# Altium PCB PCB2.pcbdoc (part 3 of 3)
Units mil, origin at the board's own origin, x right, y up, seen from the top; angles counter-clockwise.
Board outline 1771.65 x 2755.61 mil, 4 copper layers (Top Layer, Inner1, Inner2, Bottom Layer), stack 62.447 mil thick; 80 components, 88 nets, 409 pads, 183 vias.
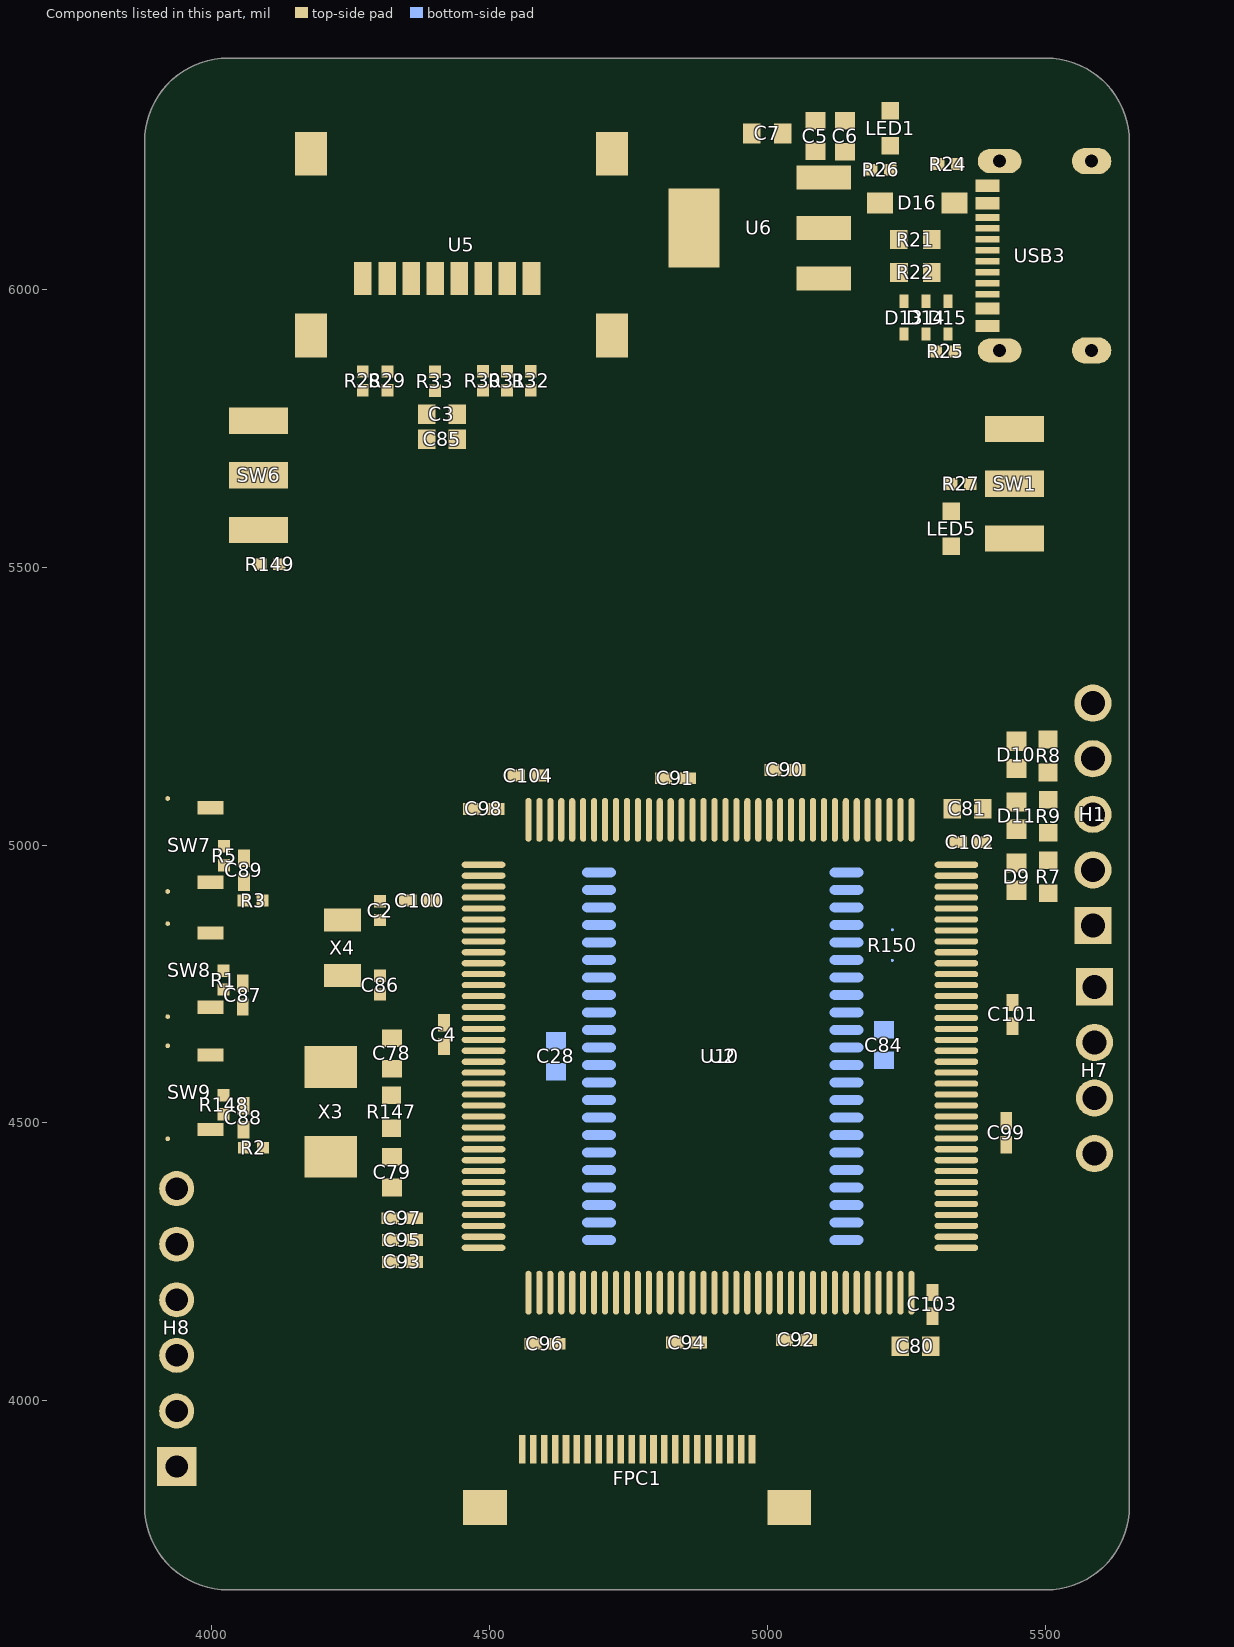
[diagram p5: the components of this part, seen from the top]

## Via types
v1: diameter 24.02, hole 12.01, Top Layer to Bottom Layer, 179 vias
v2: diameter 90.55, hole 82.68, Top Layer to Bottom Layer, 4 vias

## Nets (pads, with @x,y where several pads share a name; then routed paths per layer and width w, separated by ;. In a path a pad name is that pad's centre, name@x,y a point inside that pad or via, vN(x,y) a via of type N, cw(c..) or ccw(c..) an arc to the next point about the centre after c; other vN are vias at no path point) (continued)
pads on no net: H8.1 H8.2 U10.1 U10.2 U10.3 U10.4 U10.5 U10.7 U10.18 U10.19 U10.20 U10.21 U10.22 U10.26 U10.27 U10.28 U10.29 U10.44 U10.45 U10.46 U10.47 U10.48 U10.49 U10.69 U10.70 U10.73 U10.74 U10.75 U10.76 U10.91 U10.92 U10.93 U10.96 U10.97 U10.110 U10.117 U10.122 U10.124 U10.125 U10.126 U10.127 U10.128 U10.129 U10.132 U10.133 U10.134 U10.135 U10.136 U10.137 U10.139 U10.140 USB3.3 USB3.9

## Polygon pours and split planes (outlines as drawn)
NRST on Top Layer (solid, remove dead copper, pour order 6): 4045,4725 4035,4735 4035,4755 4015,4755 3980,4720 3970,4720 3970,4695 4040,4695 4045,4690 4065,4690 4070,4695 4070,4725
$1N25234 on Top Layer (solid, remove dead copper, pour order 8): 4035,4530 4035,4515 4045,4505 4070,4505 4070,4445 4046.71,4445 4016.71,4475 3975,4475 3970,4480 3970,4500 4005,4500 4010,4505 4010,4530
$1N25235 on Top Layer (solid, remove dead copper, pour order 10): 4045.97,4889.03 4015,4920 3975,4920 3970,4925 3970,4940 3975,4945 4005,4945 4010,4950 4010,4975 4035,4975 4035,4960 4045,4950 4070,4950 4070,4889.03
$1N4774 on Top Layer (solid, remove dead copper, pour order 12): 5545,5535 5535,5525 5395,5525 5390,5530 5390,5575 5395,5580 5535,5580 5545,5570
3.3V on Top Layer (solid, remove dead copper, pour order 14): 5300,4990 5300,4960 5305,4955 5375,4955 5385,4965 5385,4970.28 5360.28,4995 5360,4995 5360,5020.14 5330.14,5020.14
$1N4201 on Top Layer (solid, pour order 0): 5328.92,5954.53 5317.05,5966.4 5317.05,5990.07 5317.06,5990.07 5361.11,5990.07 5374.75,5976.43 5427.54,5976.43 5430.42,5973.54 5430.42,5965.98 5418.98,5954.53
5V_USB on Top Layer (solid, pour order 2): 5136.9,6178.59 5052.49,6178.59 5052.49,6252.34 5067.49,6267.35 5158.67,6267.35 5227.04,6198.98 5227.04,6136.5 5226.8,6136.26 5179.23,6136.26
$1N4593 on Top Layer (solid, pour order 4): 4990,6300 4990,6195 5050,6135 5150,6135 5155,6130 5155,6090 5150,6085 4965,6085 4915,6035 4825,6035 4820,6040 4820,6180 4825,6185 4880,6185 4955,6260 4955,6300
3.3V on Top Layer (solid, remove dead copper, pour order 16): 5285,4235 5255,4235 5253.19,4233.19 5253.19,4158.99 5257.15,4155.04 5262.48,4155.04 5285.73,4178.29 5310.09,4178.29 5310.11,4178.31 5310.11,4209.89
3.3V on Top Layer (solid, remove dead copper, pour order 18): 4530,4360 4530,4332.35 4526.42,4328.78 4399.28,4328.78 4382.24,4311.73 4382.24,4238.13 4350.18,4238.13 4348.8,4239.51 4348.8,4340.25 4368.49,4359.94 4482.22,4359.94 4482.28,4360
3.3V on Top Layer (solid, remove dead copper, pour order 20): 4575,5005 4540,5005 4495,5050 4495,5080 4500,5085 4580,5085 4580,5010
5V_USB on Top Layer (solid, remove dead copper, pour order 22): 4825,3890 4830,3885 4980,3885 4985,3890 4985,3935 4980,3940 4830,3940 4825,3935
GND on Top Layer (solid, remove dead copper, pour order 24): 3710,6670 6060,6670 6060,3550 3710,3550
GND on Bottom Layer (solid, remove dead copper, pour order 26): 3595,6825 6195,6825 6195,3000 3595,3000
GND on Inner1 (solid, remove dead copper): 3345,6830 6970,6830 6970,3350 3345,3350
GND on Inner2 (solid, remove dead copper): 3000,6645 7185,6645 7185,3075 3000,3075
5V_USB on Inner2 (solid, remove dead copper): 5145,6240 5195,6240 5210,6225 5210,6180 5205,6175 5145,6175

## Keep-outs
Board Outline Layer:
  the board outline again, w10

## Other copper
Top Layer:
  drawing of 189 lines, arcs and shapes, not listed
Inner1:
  region net 3.3V: 5519.95,4703.19 5519.95,4726.81 ccw(c5519.95,4771.1) 5555.39,4744.53 5555.39,4711.44 ccw(c5555.39,4631.28)
  region net 3.3V: 5536.74,4756.55 5526.8,4799.9 ccw(c5617.53,4890.63) 5555.39,4778.37 5555.39,4725.09 ccw(c5484.59,4704.4)
  region net NRST: 4426.35,4493 4426.35,4487 4424.82,4486.87 4423.6,4486.48 4422.59,4485.89 4421.72,4485.12 4420.05,4483.2 4417.94,4480.99 4417.94,4499.01 4420.05,4496.8 4421.72,4494.88 4422.59,4494.11 4423.6,4493.52 4424.82,4493.13
  region net A2: 4990.3,4860.86 4984.3,4860.86 4984.16,4862.39 4983.78,4863.61 4983.19,4864.62 4982.42,4865.49 4980.5,4867.16 4978.29,4869.27 4996.31,4869.27 4994.1,4867.16 4992.18,4865.49 4991.41,4864.62 4990.82,4863.61 4990.43,4862.39
  region net A1: 4963.19,4834.15 4957.19,4834.15 4957.05,4835.68 4956.67,4836.9 4956.08,4837.91 4955.31,4838.78 4953.39,4840.45 4951.18,4842.56 4969.2,4842.56 4966.99,4840.45 4965.07,4838.78 4964.3,4837.91 4963.71,4836.9 4963.32,4835.68
  region net A0: 4611.35,4793 4611.35,4787 4609.82,4786.87 4608.6,4786.48 4607.59,4785.89 4606.72,4785.12 4605.05,4783.2 4602.94,4780.99 4602.94,4799.01 4605.05,4796.8 4606.72,4794.88 4607.59,4794.11 4608.6,4793.52 4609.82,4793.13
  region net IO7: 5086.8,4460.32 5082.56,4464.56 5083.54,4465.74 5084.14,4466.87 5084.43,4468 5084.51,4469.16 5084.32,4471.7 5084.26,4474.75 5096.99,4462.02 5093.94,4462.08 5091.4,4462.26 5090.24,4462.19 5089.11,4461.9 5087.98,4461.3
  region net IO7: 5077,4300.56 5083,4302.08 5083.14,4300.59 5083.54,4299.35 5084.17,4298.3 5084.97,4297.37 5087,4295.65 5089.32,4293.68 5071.37,4292.15 5072.42,4293.41 5073.44,4294.4 5075.24,4296 5075.96,4296.82 5076.52,4297.78 5076.87,4298.99
  region net NRST: 5458.65,4917 5458.65,4923 5460.18,4923.13 5461.4,4923.52 5462.41,4924.11 5463.28,4924.88 5464.95,4926.8 5467.06,4929.01 5467.06,4910.99 5464.95,4913.2 5463.28,4915.12 5462.41,4915.89 5461.4,4916.48 5460.18,4916.87
  region net 3.3V: 4640.16,4100.88 4623.45,4084.18 4613.13,4094.23 4630.11,4111.21
  region net 3.3V: 4835.59,4053.19 4835.59,4076.81 4850,4077.01 4850,4052.99
  region net 3.3V: 5424.41,4726.81 5424.41,4703.19 5410,4702.99 5410,4727.01
  region net 3.3V: 4376.46,4926.84 4393.16,4943.54 4403.49,4933.49 4386.51,4916.51
  region net 3.3V: 4114.41,4991.81 4114.41,4968.19 4100,4967.99 4100,4992.01
  region net 3.3V: 5338.22,4968.19 5338.22,4991.81 5352.63,4992.01 5352.63,4967.99
  region net 3.3V: 5367.04,4991.81 5367.04,4968.19 5352.63,4967.99 5352.63,4992.01
  region net 3.3V: 5226.84,4918.54 5243.54,4901.84 5233.49,4891.51 5216.51,4908.49
Inner2:
  region net 3.3V: 5542.86,4774.2 5559.56,4790.9 ccw(c5597.14,4841.01) 5597.14,4778.37 5555.39,4736.62 ccw(c5492.75,4736.62)
  region net A18: 4770.9,4448.05 4769.98,4442.05 4768.39,4441.93 4767.18,4441.59 4766.25,4441.07 4765.48,4440.39 4763.92,4438.68 4762.9,4437.72 4761.57,4436.72 4764.15,4454.55 4765.06,4453.34 4765.77,4452.16 4766.96,4450.08 4767.62,4449.25 4768.44,4448.61 4769.5,4448.2
  region net A18: 5378.22,4450.01 5379.28,4456.01 5380.83,4456.14 5382.05,4456.5 5383.03,4457.07 5383.86,4457.8 5385.48,4459.65 5386.46,4460.68 5387.69,4461.76 5386.62,4443.78 5384.61,4446.06 5382.9,4448.06 5381.99,4448.86 5380.95,4449.47 5379.72,4449.87
  region net CS: 4998.68,4985.56 4994.44,4981.32 4993.27,4982.31 4992.13,4982.9 4991,4983.2 4989.84,4983.27 4987.3,4983.08 4984.25,4983.02 4996.98,4995.75 4996.92,4992.7 4996.73,4990.16 4996.8,4989 4997.1,4987.87 4997.69,4986.73
  region net CS: 5213.65,4812.01 5213.65,4817.99 5215.18,4818.13 5216.4,4818.51 5217.41,4819.1 5218.28,4819.87 5219.95,4821.8 5222.06,4824.01 5222.06,4805.99 5219.95,4808.2 5218.28,4810.13 5217.41,4810.9 5216.4,4811.49 5215.18,4811.87
  region net 5V_USB: 5171.81,6175.59 5148.19,6175.59 5147.99,6190 5172.01,6190
  region net 5V_USB: 5009.41,3936.81 5009.41,3913.19 4995,3912.99 4995,3937.01
  region net 3.3V: 5526.81,5635.59 5503.19,5635.59 5502.99,5650 5527.01,5650
Bottom Layer:
  region net $1N4774: 5617.23,4894.99 5625.58,4886.64 ccw(c5650.64,4867.84) 5619.32,4867.84 5598.44,4888.72 ccw(c5598.44,4920.04)
  region net GND: 4646.72,4638.75 4646.72,4632.75 ccw(c4646.72,4589.1) 4637.72,4631.81 4637.72,4643.25 ccw(c4646.72,4650)
  region net 3.3V: 4605.86,4568.34 4593.93,4578.69 ccw(c4560.53,4603.74) 4602.28,4603.74 4630.91,4576.69 ccw(c4630.91,4534.93)
  region net 3.3V: 4646.72,4607.25 4646.72,4601.25 ccw(c4646.72,4590) 4637.72,4596.75 4637.72,4608.19 ccw(c4646.72,4650.9)
  region net 3.3V: 4593.93,4607.37 4607.04,4616.54 ccw(c4632.09,4649.95) 4632.09,4608.19 4602.28,4582.32 ccw(c4560.53,4582.32)
  region net GND: 5183.28,4601.25 5183.28,4607.25 ccw(c5183.28,4618.5) 5192.28,4611.75 5192.28,4596.75 ccw(c5183.28,4590)
  region net GND: 5233.19,4607.25 5233.19,4601.25 ccw(c5233.19,4595.67) 5227.72,4596.75 5227.72,4611.75 ccw(c5233.19,4612.83)
  region net 3.3V: 5196.32,4647.08 5186.06,4645.31 ccw(c5044.31,4787.05) 5192.28,4651.81 5204.31,4651.81 ccw(c5209.57,4633.83)
  region net 3.3V: 5263.15,4679.37 5263.15,4655.75 ccw(c5263.15,4494.33) 5227.72,4651.81 5227.72,4683.31 ccw(c5263.15,4840.79)
  region net 3.3V: 3963.29,4420 3976.76,4400.06 3974.62,4397.58 3972.99,4394.99 3971.76,4392.28 3970.86,4389.45 3970.2,4386.5 3969.67,4383.43 3968.71,4376.92 3938.7,4413.41 3942,4413.35 3945.35,4413.45 3948.68,4413.74 3951.95,4414.28 3955.1,4415.13 3958.08,4416.33 3960.83,4417.93
  region net A4: 5107.31,4947.71 5107.31,4953.71 5108.77,4953.81 5110.01,4954.1 5111.08,4954.54 5112.05,4955.12 5113.97,4956.56 5116.31,4958.21 5116.31,4943.21 5113.97,4944.86 5112.05,4946.3 5111.08,4946.88 5110.01,4947.32 5108.77,4947.61
  region net A3: 5108.25,4916.21 5108.25,4922.21 5109.68,4922.31 5110.8,4922.6 5111.72,4923.04 5112.52,4923.62 5114.12,4925.06 5116.31,4926.71 5116.31,4911.71 5114.12,4913.36 5112.52,4914.8 5111.72,4915.38 5110.8,4915.82 5109.68,4916.11
  region net A1: 5107.31,4853.22 5107.31,4859.22 5108.77,4859.32 5110.01,4859.61 5111.08,4860.05 5112.05,4860.63 5113.97,4862.07 5116.31,4863.72 5116.31,4848.72 5113.97,4850.37 5112.05,4851.81 5111.08,4852.39 5110.01,4852.83 5108.77,4853.12
  region net A0: 5107.31,4821.72 5107.31,4827.72 5108.77,4827.82 5110.01,4828.11 5111.08,4828.55 5112.05,4829.13 5113.97,4830.57 5116.31,4832.22 5116.31,4817.22 5113.97,4818.87 5112.05,4820.31 5111.08,4820.89 5110.01,4821.33 5108.77,4821.62
  region net CS: 5178.01,4796.23 5178.01,4790.23 5176.55,4790.13 5175.31,4789.84 5174.24,4789.4 5173.27,4788.82 5171.35,4787.38 5169.01,4785.73 5169.01,4800.73 5171.35,4799.08 5173.27,4797.64 5174.24,4797.06 5175.31,4796.62 5176.55,4796.33
  region net IO0: 5178.01,4764.73 5178.01,4758.73 5176.55,4758.63 5175.31,4758.34 5174.24,4757.9 5173.27,4757.32 5171.35,4755.88 5169.01,4754.23 5169.01,4769.23 5171.35,4767.58 5173.27,4766.14 5174.24,4765.56 5175.31,4765.12 5176.55,4764.83
  region net IO1: 5178.01,4733.24 5178.01,4727.24 5176.55,4727.14 5175.31,4726.85 5174.24,4726.41 5173.27,4725.83 5171.35,4724.39 5169.01,4722.74 5169.01,4737.74 5171.35,4736.09 5173.27,4734.65 5174.24,4734.07 5175.31,4733.63 5176.55,4733.34
  region net IO2: 5178.01,4701.74 5178.01,4695.74 5176.55,4695.64 5175.31,4695.35 5174.24,4694.91 5173.27,4694.33 5171.35,4692.89 5169.01,4691.24 5169.01,4706.24 5171.35,4704.59 5173.27,4703.15 5174.24,4702.57 5175.31,4702.13 5176.55,4701.84
  region net IO3: 5107.31,4664.24 5107.31,4670.24 5108.77,4670.34 5110.01,4670.63 5111.08,4671.07 5112.05,4671.65 5113.97,4673.09 5116.31,4674.74 5116.31,4659.74 5113.97,4661.39 5112.05,4662.83 5111.08,4663.41 5110.01,4663.85 5108.77,4664.14
  region net 3.3V: 5178.01,4638.75 5178.01,4632.75 5176.55,4632.65 5175.31,4632.36 5174.24,4631.92 5173.27,4631.34 5171.35,4629.9 5169.01,4628.25 5169.01,4643.25 5171.35,4641.6 5173.27,4640.16 5174.24,4639.58 5175.31,4639.14 5176.55,4638.85
  region net GND: 5178.01,4607.25 5178.01,4601.25 5176.55,4601.15 5175.31,4600.86 5174.24,4600.42 5173.27,4599.84 5171.35,4598.4 5169.01,4596.75 5169.01,4611.75 5171.35,4610.1 5173.27,4608.66 5174.24,4608.08 5175.31,4607.64 5176.55,4607.35
  region net IO4: 5108.39,4568.54 5106.31,4574.54 5107.7,4574.65 5108.95,4574.97 5110.09,4575.46 5111.15,4576.1 5113.19,4577.7 5115.31,4579.54 5117.39,4564.69 5115.95,4565.41 5114.82,4566.1 5113.05,4567.33 5112.19,4567.83 5111.2,4568.21 5109.97,4568.45
  region net IO5: 5107.31,4538.26 5107.31,4544.26 5108.77,4544.36 5110.01,4544.65 5111.08,4545.09 5112.05,4545.67 5113.97,4547.11 5116.31,4548.76 5116.31,4533.76 5113.97,4535.41 5112.05,4536.85 5111.08,4537.43 5110.01,4537.87 5108.77,4538.16
  region net IO6: 5107.31,4506.76 5107.31,4512.76 5108.77,4512.86 5110.01,4513.15 5111.08,4513.59 5112.05,4514.17 5113.97,4515.61 5116.31,4517.26 5116.31,4502.26 5113.97,4503.91 5112.05,4505.35 5111.08,4505.93 5110.01,4506.37 5108.77,4506.66
  region net IO7: 5105.93,4477 5108.87,4483 5109.89,4483.12 5111.01,4483.43 5113.43,4484.44 5115.82,4485.61 5117.87,4486.53 5114.93,4471.83 5112.89,4473.73 5110.81,4475.38 5109.71,4476.05 5108.54,4476.56 5107.29,4476.88
  region net WE: 5107.31,4443.77 5107.31,4449.77 5108.77,4449.87 5110.01,4450.16 5111.08,4450.6 5112.05,4451.18 5113.97,4452.62 5116.31,4454.27 5116.31,4439.27 5113.97,4440.92 5112.05,4442.36 5111.08,4442.94 5110.01,4443.38 5108.77,4443.67
  region net A16: 5178.01,4418.28 5178.01,4412.28 5176.55,4412.18 5175.31,4411.89 5174.24,4411.45 5173.27,4410.87 5171.35,4409.43 5169.01,4407.78 5169.01,4422.78 5171.35,4421.13 5173.27,4419.69 5174.24,4419.11 5175.31,4418.67 5176.55,4418.38
  region net A15: 5173.7,4386.78 5173.7,4380.78 5172.96,4380.63 5172.32,4380.24 5171.23,4378.95 5170.21,4377.46 5169.65,4376.8 5169.01,4376.28 5169.01,4391.28 5169.65,4390.76 5170.21,4390.1 5171.23,4388.61 5172.32,4387.32 5172.96,4386.93
  region net A5: 4732.69,4953.71 4732.69,4947.71 4731.23,4947.61 4729.99,4947.32 4728.92,4946.88 4727.95,4946.3 4726.03,4944.86 4723.69,4943.21 4723.69,4958.21 4726.03,4956.56 4727.95,4955.12 4728.92,4954.54 4729.99,4954.1 4731.23,4953.81
  region net A7: 4729.52,4890.72 4729.52,4884.72 4728.73,4884.57 4727.97,4884.18 4726.49,4882.89 4725.07,4881.4 4723.69,4880.22 4723.69,4895.22 4725.07,4894.04 4726.49,4892.55 4727.97,4891.26 4728.73,4890.87
  region net UB: 4661.99,4821.72 4661.99,4827.72 4663.45,4827.82 4664.69,4828.11 4665.76,4828.55 4666.73,4829.13 4668.65,4830.57 4670.99,4832.22 4670.99,4817.22 4668.65,4818.87 4666.73,4820.31 4665.76,4820.89 4664.69,4821.33 4663.45,4821.62
  region net LB: 4661.99,4790.23 4661.99,4796.23 4663.45,4796.33 4664.69,4796.62 4665.76,4797.06 4666.73,4797.64 4668.65,4799.08 4670.99,4800.73 4670.99,4785.73 4668.65,4787.38 4666.73,4788.82 4665.76,4789.4 4664.69,4789.84 4663.45,4790.13
  region net IO15: 4732.69,4764.73 4732.69,4758.73 4731.23,4758.63 4729.99,4758.34 4728.92,4757.9 4727.95,4757.32 4726.03,4755.88 4723.69,4754.23 4723.69,4769.23 4726.03,4767.58 4727.95,4766.14 4728.92,4765.56 4729.99,4765.12 4731.23,4764.83
  region net IO14: 4732.69,4733.24 4732.69,4727.24 4731.23,4727.14 4729.99,4726.85 4728.92,4726.41 4727.95,4725.83 4726.03,4724.39 4723.69,4722.74 4723.69,4737.74 4726.03,4736.09 4727.95,4734.65 4728.92,4734.07 4729.99,4733.63 4731.23,4733.34
  region net IO13: 4732.69,4701.74 4732.69,4695.74 4731.23,4695.64 4729.99,4695.35 4728.92,4694.91 4727.95,4694.33 4726.03,4692.89 4723.69,4691.24 4723.69,4706.24 4726.03,4704.59 4727.95,4703.15 4728.92,4702.57 4729.99,4702.13 4731.23,4701.84
  region net IO12: 4732.69,4670.24 4732.69,4664.24 4731.23,4664.14 4729.99,4663.85 4728.92,4663.41 4727.95,4662.83 4726.03,4661.39 4723.69,4659.74 4723.69,4674.74 4726.03,4673.09 4727.95,4671.65 4728.92,4671.07 4729.99,4670.63 4731.23,4670.34
  region net GND: 4661.99,4632.75 4661.99,4638.75 4663.45,4638.85 4664.69,4639.14 4665.76,4639.58 4666.73,4640.16 4668.65,4641.6 4670.99,4643.25 4670.99,4628.25 4668.65,4629.9 4666.73,4631.34 4665.76,4631.92 4664.69,4632.36 4663.45,4632.65
  region net 3.3V: 4661.99,4601.25 4661.99,4607.25 4663.45,4607.35 4664.69,4607.64 4665.76,4608.08 4666.73,4608.66 4668.65,4610.1 4670.99,4611.75 4670.99,4596.75 4668.65,4598.4 4666.73,4599.84 4665.76,4600.42 4664.69,4600.86 4663.45,4601.15
  region net IO11: 4732.69,4575.76 4732.69,4569.76 4731.23,4569.66 4729.99,4569.37 4728.92,4568.93 4727.95,4568.35 4726.03,4566.91 4723.69,4565.26 4723.69,4580.26 4726.03,4578.61 4727.95,4577.17 4728.92,4576.59 4729.99,4576.15 4731.23,4575.86
  region net IO10: 4732.69,4544.26 4732.69,4538.26 4731.23,4538.16 4729.99,4537.87 4728.92,4537.43 4727.95,4536.85 4726.03,4535.41 4723.69,4533.76 4723.69,4548.76 4726.03,4547.11 4727.95,4545.67 4728.92,4545.09 4729.99,4544.65 4731.23,4544.36
  region net IO9: 4732.69,4512.76 4732.69,4506.76 4731.23,4506.66 4729.99,4506.37 4728.92,4505.93 4727.95,4505.35 4726.03,4503.91 4723.69,4502.26 4723.69,4517.26 4726.03,4515.61 4727.95,4514.17 4728.92,4513.59 4729.99,4513.15 4731.23,4512.86
  region net IO8: 4733.55,4480.22 4731.77,4474.22 4730.21,4474.13 4728.98,4473.88 4727.98,4473.49 4727.1,4472.99 4725.31,4471.72 4722.77,4470.27 4724.55,4485.17 4726.71,4483.35 4728.73,4481.77 4729.78,4481.13 4730.91,4480.65 4732.15,4480.33
  region net A18: 4732.69,4449.77 4732.69,4443.77 4731.23,4443.67 4729.99,4443.38 4728.92,4442.94 4727.95,4442.36 4726.03,4440.92 4723.69,4439.27 4723.69,4454.27 4726.03,4452.62 4727.95,4451.18 4728.92,4450.6 4729.99,4450.16 4731.23,4449.87
  region net A8: 4732.69,4418.28 4732.69,4412.28 4731.23,4412.18 4729.99,4411.89 4728.92,4411.45 4727.95,4410.87 4726.03,4409.43 4723.69,4407.78 4723.69,4422.78 4726.03,4421.13 4727.95,4419.69 4728.92,4419.11 4729.99,4418.67 4731.23,4418.38
  region net A11: 4729.9,4324.6 4729.9,4318.6 4729.15,4318.45 4728.41,4318.02 4726.98,4316.63 4725.62,4315.02 4724.36,4313.75 4722.98,4328.69 4724.6,4327.62 4726.35,4326.26 4728.14,4325.1 4729.03,4324.74
  region net A17: 4732.8,4292.16 4732.58,4286.16 4731.1,4286.06 4729.87,4285.78 4728.81,4285.34 4727.85,4284.77 4725.94,4283.35 4723.58,4281.72 4723.8,4296.72 4726.12,4295.04 4728.05,4293.58 4729.04,4293 4730.11,4292.55 4731.35,4292.26
  region net 3.3V: 5213.19,4896.6 5236.81,4896.6 ccw(c6236.71,4896.6) 5237.44,4861.17 5236.81,4861.28 5213.19,4861.28 5212.57,4861.17 ccw(c4205.26,4896.6)
  region net CS: 5199.07,4790.23 5199.07,4796.23 ccw(c5199.07,4808.19) 5208.07,4800.32 5208.07,4796.23 5208.07,4790.23 5208.07,4785.73 ccw(c5199.07,4778.98)
  region net CS: 5222.01,4810 5227.99,4810 ccw(c5232.48,4810.78) 5232.48,4806.22 5227.99,4806.22 5222.01,4806.22 5217.52,4806.22 ccw(c5217.52,4810.78)
  region net $1N4774: 5546.35,5560.91 5546.35,5549.09 5544.26,5548.84 5541.92,5548.15 5539.69,5547.16 5537.94,5545.99 5537.94,5564.01 5539.69,5562.84 5541.92,5561.85 5544.26,5561.16
  region net DAISY: 4714.39,4148.65 4720.39,4148.65 4720.52,4147.12 4720.9,4145.9 4721.5,4144.89 4722.26,4144.02 4724.19,4142.35 4726.39,4140.24 4708.38,4140.24 4710.59,4142.35 4712.51,4144.02 4713.28,4144.89 4713.87,4145.9 4714.25,4147.12
  region net DAISY: 4558.68,4285.56 4554.44,4281.32 4553.26,4282.3 4552.13,4282.9 4551,4283.19 4549.84,4283.26 4547.3,4283.08 4544.25,4283.02 4556.98,4295.75 4556.92,4292.7 4556.74,4290.16 4556.81,4289 4557.1,4287.87 4557.7,4286.74
  region net USB_OTG_FS_DM: 5432.07,4864.08 5432.07,4858.08 5430.54,4857.94 5429.32,4857.56 5428.31,4856.97 5427.44,4856.2 5425.77,4854.27 5423.66,4852.07 5423.66,4870.08 5425.77,4867.88 5427.44,4865.95 5428.31,4865.18 5429.32,4864.59 5430.54,4864.21
  region net USB_OTG_FS_DP: 5432.19,4894.18 5432.19,4888.18 5430.67,4888.04 5429.44,4887.66 5428.44,4887.07 5427.56,4886.3 5425.9,4884.38 5423.79,4882.17 5423.79,4900.18 5425.9,4897.98 5427.56,4896.05 5428.44,4895.29 5429.44,4894.69 5430.67,4894.31
  region net USB_OTG_FS_DM: 5339.68,5812.07 5333.68,5800.42 5333.57,5801.87 5333.25,5803.29 5332.74,5804.65 5332.03,5805.89 5331.15,5806.98 5330.09,5807.86 5328.88,5808.49 5327.53,5808.83 5340.95,5820.48 5340.71,5817.97 5340.28,5816.27 5339.87,5814.58
  region net RST(ADS8688): 4813.14,3978 4813.14,3972 4811.61,3971.87 4810.39,3971.48 4809.38,3970.89 4808.51,3970.12 4806.84,3968.2 4804.73,3965.99 4804.73,3984.01 4806.84,3981.8 4808.51,3979.88 4809.38,3979.11 4810.39,3978.52 4811.61,3978.13
  region net RST(ADS8688): 5423.68,4785.56 5419.44,4781.32 5418.26,4782.3 5417.13,4782.9 5416,4783.19 5414.84,4783.26 5412.3,4783.08 5409.25,4783.02 5421.98,4795.75 5421.92,4792.7 5421.74,4790.16 5421.81,4789 5422.1,4787.87 5422.7,4786.74
  region net WKUP: 4408.65,4302 4408.65,4308 4410.18,4308.13 4411.4,4308.52 4412.41,4309.11 4413.28,4309.88 4414.95,4311.8 4417.06,4314.01 4417.06,4295.99 4414.95,4298.2 4413.28,4300.12 4412.41,4300.89 4411.4,4301.48 4410.18,4301.87
  region net WKUP: 4096.02,4417.41 4090.02,4417.41 4089.89,4418.94 4089.5,4420.16 4088.91,4421.17 4088.14,4422.04 4086.22,4423.71 4084.01,4425.82 4102.03,4425.82 4099.82,4423.71 4097.9,4422.04 4097.13,4421.17 4096.54,4420.16 4096.16,4418.94
  region net NRST: 4095.31,4695.56 4091.07,4691.32 4089.89,4692.3 4088.76,4692.9 4087.63,4693.19 4086.47,4693.26 4083.93,4693.08 4080.88,4693.02 4093.61,4705.75 4093.55,4702.7 4093.36,4700.16 4093.44,4699 4093.73,4697.87 4094.33,4696.74
  region net NRST: 4396.32,4499.44 4400.56,4503.68 4401.74,4502.7 4402.87,4502.1 4404,4501.81 4405.16,4501.74 4407.7,4501.92 4410.75,4501.98 4398.02,4489.25 4398.08,4492.3 4398.26,4494.84 4398.19,4496 4397.9,4497.13 4397.3,4498.26
  region net UB: 4639.4,4967.51 4633.4,4967.51 4633.26,4968.9 4632.86,4969.91 4632.23,4970.64 4631.41,4971.19 4629.36,4972.21 4628.21,4972.89 4627.02,4973.82 4644.93,4975.72 4643.9,4974.45 4642.9,4973.47 4641.13,4971.95 4640.42,4971.18 4639.88,4970.26 4639.53,4969.07
  region net A5: 4783.08,4947.71 4783.57,4953.71 4785.1,4953.84 4786.32,4954.22 4787.32,4954.8 4788.17,4955.55 4789.81,4957.43 4790.78,4958.49 4791.97,4959.59 4791.44,4941.59 4789.38,4943.84 4787.71,4945.8 4786.83,4946.58 4785.82,4947.18 4784.59,4947.57
  region net A6: 4808.65,4916.21 4808.65,4922.21 4810.18,4922.34 4811.4,4922.73 4812.41,4923.32 4813.28,4924.09 4814.95,4926.01 4817.06,4928.22 4817.06,4910.2 4814.95,4912.41 4813.28,4914.33 4812.41,4915.1 4811.4,4915.69 4810.18,4916.08
  region net IO13: 4973.88,4692.66 4978.12,4696.91 4979.3,4695.92 4980.43,4695.33 4981.56,4695.03 4982.72,4694.96 4985.26,4695.14 4988.31,4695.21 4975.58,4682.47 4975.65,4685.53 4975.83,4688.06 4975.75,4689.22 4975.46,4690.35 4974.86,4691.49
  region net IO12: 5025.2,4490.56 5028.13,4496.11 5029.29,4495.16 5030.45,4494.57 5031.65,4494.26 5032.88,4494.18 5035.56,4494.39 5038.59,4494.67 5027.22,4480.7 5027.05,4482.33 5027.05,4483.75 5027.18,4486.13 5027.11,4487.2 5026.83,4488.26 5026.22,4489.36
  region net IO11: 5025.39,4438.08 5029.63,4442.32 5030.8,4441.34 5031.94,4440.74 5033.07,4440.45 5034.23,4440.38 5036.77,4440.56 5039.82,4440.63 5027.08,4427.89 5027.15,4430.94 5027.33,4433.48 5027.26,4434.64 5026.97,4435.77 5026.37,4436.91
  region net IO8: 5023.38,4329.07 5022.47,4335.07 5023.98,4335.21 5025.21,4335.6 5026.24,4336.22 5027.15,4337.01 5028.85,4338.99 5030.88,4341.27 5031.78,4323.28 5030.57,4324.36 5029.59,4325.41 5027.96,4327.26 5027.12,4328 5026.14,4328.57 5024.92,4328.94
  region net A9: 4911.06,4380.78 4911.28,4386.78 4912.81,4386.91 4914.04,4387.29 4915.04,4387.88 4915.9,4388.64 4917.56,4390.55 4918.52,4391.62 4919.69,4392.73 4919.47,4374.72 4917.38,4376.95 4915.7,4378.89 4914.82,4379.66 4913.81,4380.26 4912.58,4380.64
  region net A11: 4956.32,4307.08 4951.88,4311.12 4952.85,4312.29 4953.45,4313.43 4953.74,4314.57 4953.82,4315.74 4953.63,4318.3 4953.53,4321.35 4966.46,4308.82 4964.85,4308.77 4963.41,4308.85 4960.89,4309.03 4959.75,4308.95 4958.63,4308.66 4957.5,4308.06
  region net A3: 4769.8,4817.4 4769.8,4811.4 4769.01,4811.2 4768.33,4810.67 4767.73,4809.89 4767.19,4808.96 4766.15,4806.96 4765.6,4806.08 4765,4805.39 4765,4823.4 4765.6,4822.71 4766.15,4821.83 4767.19,4819.84 4767.73,4818.9 4768.33,4818.12 4769.01,4817.59
  region net A0: 4950.15,4827.72 4955.55,4821.72 4954.13,4821.57 4952.85,4821.13 4951.68,4820.46 4950.62,4819.59 4948.76,4817.41 4947.14,4814.91 4941.74,4832.09 4943.71,4830.95 4945.86,4829.5 4948.04,4828.25 4949.11,4827.86
  region net IO0: 5187.44,4758.73 5190.03,4764.73 5191.63,4764.85 5192.83,4765.19 5193.76,4765.71 5194.53,4766.39 5196.09,4768.1 5197.1,4769.06 5198.44,4770.06 5195.84,4752.23 5193.97,4754.62 5192.2,4756.7 5191.24,4757.53 5190.16,4758.17 5188.91,4758.58
  region net IO1: 5209.64,4727 5209.64,4733 5211.17,4733.13 5212.39,4733.52 5213.4,4734.11 5214.27,4734.88 5215.94,4736.8 5218.05,4739.01 5218.05,4720.99 5215.94,4723.2 5214.27,4725.12 5213.4,4725.89 5212.39,4726.48 5211.17,4726.87
  region net IO2: 5163.65,4695.74 5163.65,4701.74 5165.18,4701.87 5166.4,4702.26 5167.41,4702.85 5168.28,4703.62 5169.95,4705.54 5172.06,4707.75 5172.06,4689.73 5169.95,4691.94 5168.28,4693.86 5167.41,4694.63 5166.4,4695.22 5165.18,4695.61
  region net IO3: 5111.35,4670.24 5111.35,4664.24 5109.82,4664.11 5108.6,4663.72 5107.59,4663.13 5106.72,4662.36 5105.05,4660.44 5102.94,4658.23 5102.94,4676.25 5105.05,4674.04 5106.72,4672.12 5107.59,4671.35 5108.6,4670.76 5109.82,4670.37
  region net IO4: 5110.12,4574.54 5110.12,4568.54 5108.6,4568.4 5107.37,4568.02 5106.37,4567.43 5105.5,4566.66 5103.83,4564.74 5101.72,4562.53 5101.72,4580.54 5103.83,4578.34 5105.5,4576.41 5106.37,4575.64 5107.37,4575.05 5108.6,4574.67
  region net IO5: 5110.36,4544.26 5112.25,4538.26 5110.76,4538.12 5109.52,4537.71 5108.46,4537.08 5107.52,4536.27 5105.78,4534.22 5103.84,4531.88 5101.95,4549.79 5103.24,4548.76 5104.24,4547.76 5105.83,4545.99 5106.63,4545.28 5107.58,4544.74 5108.79,4544.38
  region net IO6: 5111.35,4512.76 5111.35,4506.76 5109.82,4506.63 5108.6,4506.24 5107.59,4505.65 5106.72,4504.88 5105.05,4502.96 5102.94,4500.75 5102.94,4518.77 5105.05,4516.56 5106.72,4514.64 5107.59,4513.87 5108.6,4513.28 5109.82,4512.89
  region net WE: 5063,4723.65 5057,4723.65 5056.87,4725.18 5056.48,4726.4 5055.89,4727.41 5055.12,4728.28 5053.2,4729.95 5050.99,4732.06 5069.01,4732.06 5066.8,4729.95 5064.88,4728.28 5064.11,4727.41 5063.52,4726.4 5063.13,4725.18
  region net A16: 5166.67,4412.28 5165.72,4418.28 5167.23,4418.42 5168.46,4418.81 5169.5,4419.43 5170.4,4420.22 5172.1,4422.21 5174.13,4424.49 5175.08,4406.5 5173.86,4407.58 5172.88,4408.62 5171.25,4410.47 5170.41,4411.21 5169.43,4411.78 5168.22,4412.15
  region net A14: 5394.59,4601.32 5390.35,4605.56 5391.33,4606.74 5391.93,4607.87 5392.22,4609 5392.3,4610.16 5392.11,4612.7 5392.05,4615.75 5404.78,4603.02 5401.73,4603.08 5399.19,4603.26 5398.03,4603.19 5396.9,4602.9 5395.77,4602.3
  region net A12: 5412.66,4547 5412.66,4553 5414.18,4553.13 5415.41,4553.52 5416.42,4554.11 5417.29,4554.88 5418.95,4556.8 5421.07,4559.01 5421.07,4540.99 5418.95,4543.2 5417.29,4545.12 5416.42,4545.89 5415.41,4546.48 5414.18,4546.87
  region net A17: 5417.94,4398.61 5411.94,4398.69 5411.81,4400.22 5411.43,4401.45 5410.84,4402.45 5410.07,4403.32 5408.15,4404.98 5405.96,4407.1 5423.97,4407.02 5421.76,4404.91 5419.83,4403.24 5419.06,4402.37 5418.46,4401.36 5418.08,4400.13
  region net IO7: 5107.03,4483 5116.03,4477 5114.68,4476.85 5113.36,4476.41 5112.09,4475.74 5110.9,4474.86 5109.84,4473.83 5108.91,4472.68 5108.17,4471.44 5107.62,4470.17 5098.62,4485.77 5100.89,4485.04 5102.8,4484.13 5104.72,4483.34 5105.8,4483.09
  region net A18: 4738.65,4443.77 4738.65,4449.77 4740.18,4449.9 4741.4,4450.29 4742.41,4450.88 4743.28,4451.65 4744.95,4453.57 4747.06,4455.78 4747.06,4437.76 4744.95,4439.97 4743.28,4441.89 4742.41,4442.66 4741.4,4443.25 4740.18,4443.64
  region net SDIO_D1: 5256.92,4812.49 5262.92,4812.49 5263.06,4810.97 5263.44,4809.74 5264.03,4808.74 5264.8,4807.86 5266.72,4806.2 5268.93,4804.09 5250.92,4804.09 5253.12,4806.2 5255.05,4807.86 5255.82,4808.74 5256.41,4809.74 5256.79,4810.97
  region net SDIO_D0: 5281.02,4779.9 5287.02,4779.9 5287.16,4778.37 5287.54,4777.15 5288.13,4776.14 5288.9,4775.27 5290.82,4773.6 5293.03,4771.49 5275.02,4771.49 5277.22,4773.6 5279.14,4775.27 5279.91,4776.14 5280.51,4777.15 5280.89,4778.37
  region net SDIO_D1: 4286.15,5868.67 4281.9,5864.43 4280.73,5865.41 4279.59,5866.01 4278.46,5866.3 4277.3,5866.38 4274.77,5866.19 4271.71,5866.13 4284.45,5878.86 4284.38,5875.81 4284.2,5873.27 4284.27,5872.11 4284.57,5870.98 4285.16,5869.85
  region net SDIO_D0: 4329.82,5869.54 4325.58,5865.29 4324.4,5866.28 4323.27,5866.87 4322.14,5867.17 4320.98,5867.24 4318.44,5867.06 4315.39,5866.99 4328.12,5879.73 4328.06,5876.67 4327.88,5874.14 4327.95,5872.98 4328.24,5871.85 4328.84,5870.71
  region net SDIO_CLK: 4405.75,5862.63 4399.75,5862.63 4399.62,5864.15 4399.23,5865.38 4398.64,5866.38 4397.87,5867.26 4395.95,5868.92 4393.74,5871.03 4411.76,5871.03 4409.55,5868.92 4407.63,5867.26 4406.86,5866.38 4406.27,5865.38 4405.88,5864.15
  region net SDIO_CMD: 4492.37,5862.63 4486.37,5862.63 4486.24,5864.15 4485.85,5865.38 4485.26,5866.38 4484.49,5867.26 4482.57,5868.92 4480.36,5871.03 4498.38,5871.03 4496.17,5868.92 4494.25,5867.26 4493.48,5866.38 4492.89,5865.38 4492.5,5864.15
  region net SDIO_D3: 4535.15,5862.1 4529.15,5862.1 4529.02,5863.62 4528.64,5864.85 4528.04,5865.86 4527.28,5866.73 4525.35,5868.39 4523.15,5870.51 4541.16,5870.51 4538.95,5868.39 4537.03,5866.73 4536.26,5865.86 4535.67,5864.85 4535.29,5863.62
  region net SDIO_D2: 4577.63,5861.93 4571.63,5861.93 4571.49,5863.46 4571.11,5864.68 4570.52,5865.69 4569.75,5866.56 4567.83,5868.23 4565.62,5870.34 4583.63,5870.34 4581.43,5868.23 4579.5,5866.56 4578.73,5865.69 4578.14,5864.68 4577.76,5863.46
  region net SDIO_CLK: 5128.65,5157 5128.65,5163 5130.18,5163.13 5131.4,5163.52 5132.41,5164.11 5133.28,5164.88 5134.95,5166.8 5137.06,5169.01 5137.06,5150.99 5134.95,5153.2 5133.28,5155.12 5132.41,5155.89 5131.4,5156.48 5130.18,5156.87
  region net SDIO_D3: 5131.32,5209.44 5135.56,5213.68 5136.74,5212.7 5137.87,5212.1 5139,5211.81 5140.16,5211.74 5142.7,5211.92 5145.75,5211.98 5133.02,5199.25 5133.08,5202.3 5133.26,5204.84 5133.19,5206 5132.9,5207.13 5132.3,5208.26
  region net SDIO_CMD: 5106.32,5190.43 5110.56,5194.67 5111.74,5193.69 5112.87,5193.09 5114,5192.8 5115.16,5192.73 5117.7,5192.91 5120.75,5192.98 5108.02,5180.24 5108.08,5183.29 5108.26,5185.83 5108.19,5186.99 5107.9,5188.12 5107.3,5189.26
  region net SDIO_D2: 5152.53,5230.65 5156.77,5234.89 5157.95,5233.91 5159.08,5233.31 5160.22,5233.02 5161.37,5232.95 5163.91,5233.13 5166.97,5233.2 5154.23,5220.46 5154.3,5223.51 5154.48,5226.05 5154.4,5227.21 5154.11,5228.34 5153.52,5229.48
  region net 3.3V: 4431.81,4379.21 4408.19,4379.21 4407.99,4393.62 4432.01,4393.62
  region net 3.3V: 4425.99,4410.75 4437.13,4399.61 4435.29,4398 4433.7,4396.63 4433.05,4395.9 4432.53,4395.07 4432.17,4394.07 4431.98,4392.87 4419.25,4405.6 4420.45,4405.79 4421.45,4406.15 4422.28,4406.67 4423.01,4407.32 4424.38,4408.91
  region net 3.3V: 4592.49,4631.09 4587.17,4614.13 4586.21,4615.25 4585.43,4616.4 4584.09,4618.47 4583.41,4619.22 4582.62,4619.67 4581.66,4619.72 4580.46,4619.3 4585.44,4635.93 4586.14,4634.94 4586.93,4634.23 4588.69,4633.29 4590.58,4632.46 4591.54,4631.88
  region net 3.3V: 4556.46,4631.84 4573.16,4648.54 4583.49,4638.49 4566.51,4621.51
  region net CS: 5227.99,4795.62 5222.01,4803.12 5221.89,4804.24 5221.58,4805.31 5220.58,4807.37 5219.42,4809.42 5218.5,4811.53 5234.88,4804.03 5232.35,4802.6 5231.19,4801.69 5230.14,4800.67 5229.26,4799.54 5228.58,4798.31 5228.15,4797
  region net 3.3V: 4561.81,5050.59 4538.19,5050.59 4537.99,5065 4562.01,5065
  region net 3.3V: 4535.59,5053.19 4535.59,5076.81 4550,5077.01 4550,5052.99
  region net 3.3V: 4551.84,5083.54 4568.54,5066.84 4558.49,5056.51 4541.51,5073.49
  region net 3.3V: 4750.59,5113.19 4750.59,5136.81 4765,5137.01 4765,5112.99
  region net 3.3V: 5395.59,4703.19 5395.59,4726.81 5410,4727.01 5410,4702.99
  region net 3.3V: 4088.16,4511.46 4071.46,4528.16 4081.51,4538.49 4098.49,4521.51
  region net 3.3V: 4067.35,4528.55 4082.89,4546.42 4084.54,4544.83 4086.3,4543.43 4088.22,4542.43 4089.26,4542.13 4090.37,4542 4078.24,4527.55 4078,4528.3 4077.64,4528.8 4077.17,4529.09 4076.61,4529.21 4075.26,4529.03 4073.7,4528.54 4072.02,4527.98 4070.34,4527.63 4069.53,4527.61 4068.75,4527.73 4068.02,4528.03
  region net 3.3V: 4408.19,4359.41 4431.81,4359.41 4432.01,4345 4407.99,4345
  region net 3.3V: 4383.19,4939.41 4406.81,4939.41 4407.01,4925 4382.99,4925
  region net 3.3V: 4111.81,4965.59 4088.19,4965.59 4087.99,4980 4112.01,4980
  region net 3.3V: 5236.81,4885.59 5213.19,4885.59 5212.99,4900 5237.01,4900

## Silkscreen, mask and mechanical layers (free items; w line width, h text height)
Top Silkscreen Layer:
  text "内置可编程电压 / 检测器（PVD） / 关闭/开启" at 3895,6275 h59.06 r270
  text "墨藤" at 4675,5605 h118.11
  text "烧录/运行" at 5480,5240 h59.06 r90
  text "GND / CLK / DIO / RST / 3.3V" at 5275,5215 h39.37
  text "BOOT0 / NRST / KEY" at 3900,5170 h59.06
  text "3.3V / GND / U_RX / U_TX" at 5405,4070 h59.06
  text "<= / <= / <=" at 4060,4030 h39.37
Bottom Silkscreen Layer:
  lines w10: 3880,3809.98 3880,5335.33 cw(c4030,5335.33) 4030,5485.33 5501.65,5485.33 cw(c5501.65,5335.33) 5651.65,5335.33 5651.65,3809.98 cw(c5501.67,3809.98) 5501.65,3660 4030,3660 cw(c4029.98,3809.98) 3880,3809.98

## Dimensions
3880,3205 to 5650,3205 on Document Layer
6325,3660 to 6325,6415 on Document Layer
